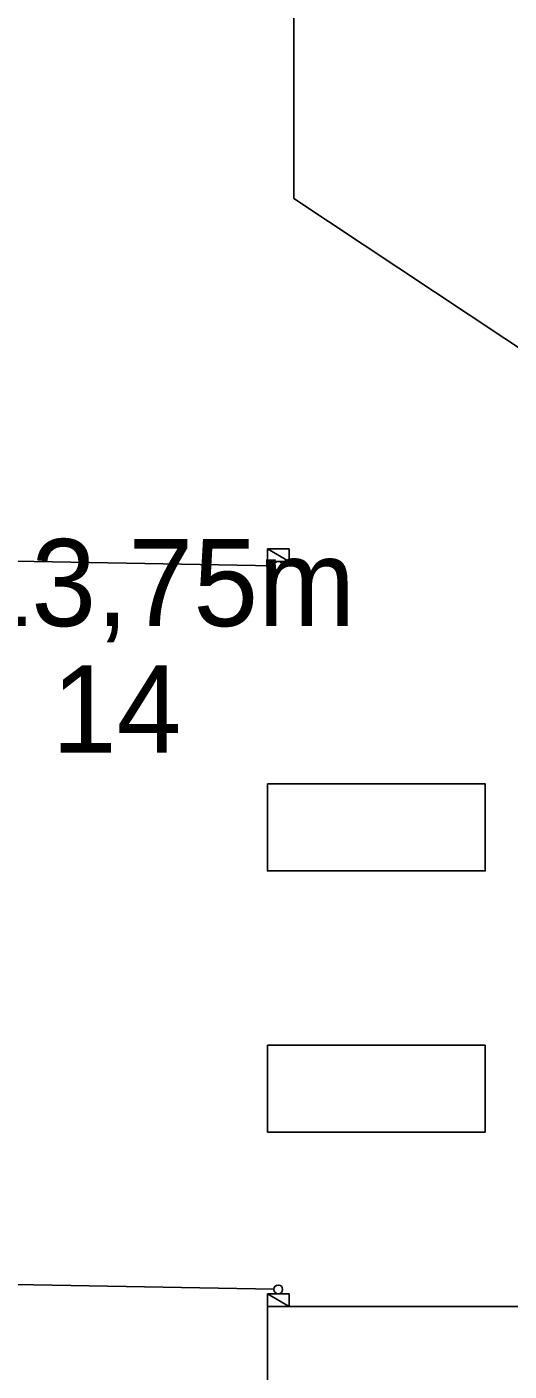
# Model space of a CAD drawing. Extents: x -263964 to -263544, y -1242317 to -1242020.
# Drawn here: x -263787.49 to -263776.42, y -1242235.87 to -1242205 of the extents above; entities that cross this region are included whole.
import ezdxf

# ---------------------------------------------------------------- set-up
doc = ezdxf.new("R2010")
doc.units = 0
for name, color, linetype in [('KFA_KOORDINACNA_SITUACIA_DSP_SEDA', 7, 'Continuous'), ('KFA_SO_50-1-II_BODY', 7, 'Continuous'), ('POPIS', 7, 'Continuous')]:
    doc.layers.add(name, color=color, linetype=linetype)

msp = doc.modelspace()

# ---------------------------------------------------------------- linework, layer by layer
at = {"layer": 'KFA_KOORDINACNA_SITUACIA_DSP_SEDA'}
for p, q in [((-263781.364, -1242208.936), (-263781.371, -1242084.903)), ((-263758.153, -1242224.365), (-263781.364, -1242208.936)), ((-263781.818, -1242217.375), (-263790.409, -1242217.218)), ((-263781.968, -1242216.987), (-263781.468, -1242216.987)), ((-263781.968, -1242217.277), (-263781.968, -1242216.987)), ((-263781.968, -1242216.987), (-263781.468, -1242217.277)), ((-263781.968, -1242216.987), (-263781.468, -1242217.277)), ((-263781.468, -1242216.987), (-263781.968, -1242216.987)), ((-263781.468, -1242216.987), (-263781.468, -1242217.277)), ((-263781.468, -1242217.277), (-263781.468, -1242216.987)), ((-263781.468, -1242217.277), (-263781.968, -1242217.277)), ((-263781.968, -1242228.382), (-263781.968, -1242230.382)), ((-263776.968, -1242228.382), (-263781.968, -1242228.382)), ((-263776.968, -1242230.382), (-263776.968, -1242228.382)), ((-263781.968, -1242230.382), (-263776.968, -1242230.382)), ((-263781.818, -1242233.99), (-263790.714, -1242233.827)), ((-263781.968, -1242234.092), (-263781.468, -1242234.092)), ((-263781.968, -1242234.382), (-263781.968, -1242234.092)), ((-263781.968, -1242234.092), (-263781.468, -1242234.382)), ((-263781.968, -1242234.092), (-263781.468, -1242234.382)), ((-263781.468, -1242234.092), (-263781.968, -1242234.092)), ((-263781.468, -1242234.092), (-263781.468, -1242234.382)), ((-263781.468, -1242234.382), (-263781.468, -1242234.092)), ((-263781.468, -1242234.382), (-263781.968, -1242234.382)), ((-263781.968, -1242234.382), (-263771.968, -1242234.382)), ((-263781.968, -1242238.382), (-263781.968, -1242234.382)), ((-263781.968, -1242234.382), (-263781.968, -1242234.382))]:
    msp.add_line(p, q, dxfattribs=at)
msp.add_lwpolyline([(-263781.968, -1242222.382), (-263776.968, -1242222.382), (-263776.968, -1242224.382), (-263781.968, -1242224.382)], close=True, dxfattribs=at)
for centre in [(-263781.718, -1242217.377), (-263781.718, -1242233.992)]:
    msp.add_circle(centre, 0.1, dxfattribs=at)

# ---------------------------------------------------------------- texts
at = {"layer": 'KFA_SO_50-1-II_BODY'}
msp.add_text('14', height=2, dxfattribs=at).set_placement((-263786.917, -1242221.664))
at = {"layer": 'POPIS'}
msp.add_text('HDPE Ø63mm - 13,75m', height=2, dxfattribs=at).set_placement((-263808.935, -1242218.76))

doc.saveas('drawing.dxf')
